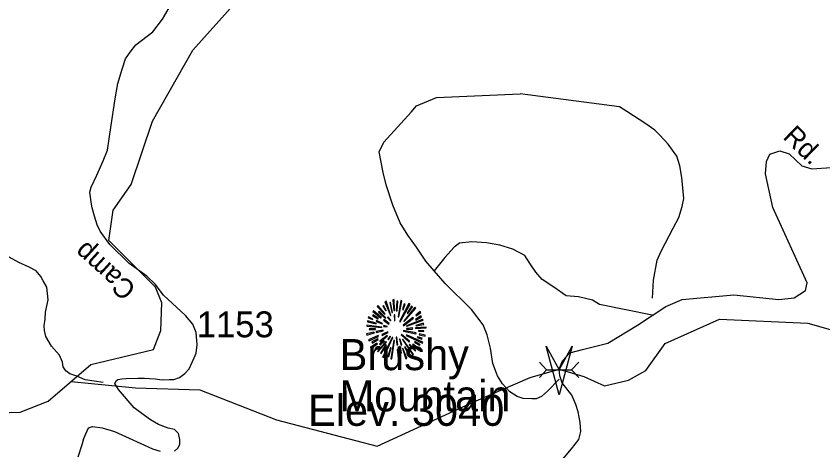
# Model space of a CAD drawing. Extents: x 990631 to 1056237, y 535999 to 585651.
# Drawn here: x 1010994 to 1014890, y 563508 to 565608 of the extents above; entities that cross this region are included whole.
import ezdxf

# ---------------------------------------------------------------- set-up
doc = ezdxf.new("R2010")
doc.units = 0
for name, color, linetype in [('Exist Geographical Mountain Summit CELL', 7, 'Continuous'), ('Exist Geographical Mountain Summit Elevation Number Label', 7, 'Continuous'), ('Exist Geographical Mountain Summit Label', 7, 'Continuous'), ('Exist Hydrographic Creek Single Shore', 7, 'Continuous'), ('Exist Road Non-System Type 51', 7, 'Continuous'), ('Exist Road Secondary Structure Pipe CELL', 7, 'Continuous'), ('Exist Road Secondary Structure Standard Bridge Attributed CELL', 7, 'Continuous'), ('Exist Road Secondary Type 41 Attributed', 7, 'Continuous'), ('Exist Road Secondary Type 51 Attributed', 7, 'Continuous'), ('Exist Road Secondary Type 51 Label', 7, 'Continuous'), ('Exist Road Secondary Type 51 Number Label', 7, 'Continuous')]:
    doc.layers.add(name, color=color, linetype=linetype)

msp = doc.modelspace()

# ---------------------------------------------------------------- linework, layer by layer
at = {"layer": 'Exist Geographical Mountain Summit CELL'}
for points in [[(1012736.6, 564205.5), (1012772.5, 564168.1), (1012775.8, 564170.6), (1012740.6, 564210.3)], [(1012764.1, 564207), (1012779.8, 564185.2), (1012781.6, 564186.6), (1012768.2, 564211)], [(1012775, 564228.8), (1012801.2, 564161.9), (1012804.2, 564163), (1012780.2, 564231.3)], [(1012808.9, 564176.8), (1012811.4, 564177.5), (1012802.4, 564225.5), (1012798, 564224.4)], [(1012813.6, 564238.2), (1012817.7, 564186.2), (1012820.9, 564186.6), (1012819.5, 564239.3)], [(1012829.6, 564184.1), (1012833.6, 564184.1), (1012837.2, 564231.3), (1012831.7, 564231.3)], [(1012841.6, 564155.7), (1012856.5, 564232.8), (1012851, 564234.6), (1012838.3, 564156.5)], [(1012844.8, 564133.9), (1012847.8, 564132.1), (1012896.4, 564216.7), (1012891, 564220.4)], [(1012859.3, 564191), (1012862.7, 564189.8), (1012872.1, 564216.7), (1012867.4, 564218.5)], [(1012903.4, 564207), (1012882.3, 564173.5), (1012885.2, 564172.4), (1012907.7, 564203.7)], [(1012715.1, 564161.9), (1012740.9, 564145.5), (1012743.1, 564148.1), (1012718, 564165.9)], [(1012716.2, 564180.8), (1012755.8, 564150.3), (1012758, 564152.5), (1012719.9, 564185.2)], [(1012744.5, 564177.9), (1012777.2, 564148.8), (1012779.4, 564151), (1012747.4, 564183)], [(1012865.9, 564135.4), (1012868.1, 564133.2), (1012923.7, 564197.5), (1012919.7, 564202.2)], [(1012923.7, 564163.4), (1012925.5, 564160.8), (1012948.4, 564177.1), (1012944.8, 564180.8)], [(1012690.4, 564131.7), (1012731.8, 564122.3), (1012732.9, 564125.6), (1012691.5, 564136.4)], [(1012693.3, 564151), (1012715.8, 564142.3), (1012716.9, 564145.2), (1012694.8, 564156.1)], [(1012731.8, 564133.9), (1012762.3, 564121.9), (1012763.5, 564124.1), (1012734, 564138)], [(1012768.2, 564139.4), (1012793.3, 564120.4), (1012795.4, 564123.3), (1012770.7, 564142.6)], [(1012787.8, 564152.5), (1012801.6, 564136), (1012803.8, 564138.2), (1012791.1, 564155.4)], [(1012819.1, 564164.8), (1012820.5, 564135.7), (1012823.1, 564136), (1012823.1, 564165.2)], [(1012862.7, 564115.4), (1012864.5, 564112.9), (1012913.1, 564148.8), (1012909.9, 564153.2)], [(1012879.7, 564112.5), (1012880.8, 564110.3), (1012958.9, 564139), (1012957.1, 564143.7)], [(1012923.7, 564140.5), (1012951.3, 564155.4), (1012948.4, 564160.4), (1012922.3, 564143)], [(1012687.8, 564110.7), (1012759.8, 564103.7), (1012760.1, 564106.6), (1012687.8, 564115.7)], [(1012699.9, 564093.2), (1012729.6, 564094.7), (1012729.6, 564098.3), (1012698.8, 564098.3)], [(1012732.2, 564084.2), (1012733.3, 564079.4), (1012766.4, 564087.8), (1012765.7, 564091.4)], [(1012768.5, 564109.6), (1012785.6, 564107.4), (1012786, 564109.6), (1012769.3, 564113.9)], [(1012864.1, 564086), (1012924.8, 564074), (1012925.9, 564078.3), (1012865.2, 564089.6)], [(1012878.7, 564099.8), (1012878.7, 564096.9), (1012908.8, 564096.9), (1012909.5, 564101.9)], [(1012921.9, 564098.7), (1012974.2, 564101.9), (1012974.6, 564106.6), (1012922.3, 564101.9)], [(1012925.5, 564112.5), (1012962.3, 564119), (1012960.8, 564124.5), (1012924.1, 564114.7)], [(1012936.8, 564086.7), (1012963.3, 564084.5), (1012963.3, 564088.8), (1012937.2, 564089.9)], [(1012686.4, 564072.9), (1012687.8, 564067.8), (1012723.9, 564078.3), (1012721.7, 564081.6)], [(1012696.2, 564045.2), (1012698.8, 564040.6), (1012744.2, 564060.5), (1012742.7, 564065.2)], [(1012713.7, 564029.3), (1012742.7, 564046), (1012740.6, 564049.6), (1012711.5, 564034.3)], [(1012750, 564038.7), (1012752.9, 564035), (1012787.4, 564063.4), (1012785.6, 564066)], [(1012759.8, 564070), (1012762, 564065.2), (1012790.7, 564080.5), (1012789.7, 564083.8)], [(1012781.6, 563998.8), (1012786, 563997), (1012812.5, 564055.4), (1012810, 564056.2)], [(1012788.5, 564048.1), (1012791.8, 564045.2), (1012802, 564061.6), (1012800.1, 564063)], [(1012828.5, 564057.3), (1012832.5, 564020.2), (1012836.9, 564020.5), (1012831.7, 564058)], [(1012844.5, 564048.5), (1012853.2, 564018.7), (1012857.2, 564020.5), (1012846.6, 564049.6)], [(1012852.9, 564068.9), (1012891.4, 564033.6), (1012893.9, 564038), (1012854.7, 564071.1)], [(1012877.9, 564066.4), (1012956.1, 564028.2), (1012957.9, 564033.6), (1012879.4, 564069.2)], [(1012931.4, 564056.2), (1012952.4, 564048.1), (1012954.2, 564052.5), (1012932.8, 564059.4)], [(1012940.8, 564069.6), (1012969.1, 564062.3), (1012969.8, 564067.8), (1012941.8, 564074)], [(1012707.5, 564008.5), (1012710.4, 564004.5), (1012738.8, 564025.6), (1012736.2, 564028.9)], [(1012738.4, 563988.9), (1012741.3, 563986.4), (1012782, 564034), (1012779.1, 564036.1)], [(1012753.7, 564020.2), (1012772.9, 564038.3), (1012769.6, 564040.6), (1012749.2, 564023.4)], [(1012778.4, 564020.2), (1012753.3, 563980.9), (1012756.5, 563978.4), (1012782.4, 564018)], [(1012803, 563953.3), (1012807.8, 563952.2), (1012820.5, 564041.6), (1012817.3, 564042.4)], [(1012854.3, 563982), (1012848.8, 564011.9), (1012845.6, 564011.9), (1012850, 563980.9)], [(1012859, 564046.3), (1012909.5, 563971.5), (1012913.1, 563974.4), (1012861.5, 564047.4)], [(1012869.5, 564009.2), (1012885.5, 563979.8), (1012889.6, 563982), (1012873.2, 564010.7)], [(1012891.4, 564020.5), (1012921.5, 563991.4), (1012924.8, 563994), (1012893.6, 564023)], [(1012908.1, 564021.2), (1012938.6, 563995.4), (1012941.8, 563999.1), (1012909.9, 564023.8)], [(1012917.2, 564032.2), (1012942.2, 564019.1), (1012944.8, 564022.7), (1012919.4, 564036.1)], [(1012763.5, 563961.7), (1012768.2, 563958.8), (1012779.1, 563983.5), (1012775.8, 563985.7)], [(1012793.3, 563963.5), (1012805.2, 564006.3), (1012801.6, 564006.7), (1012788.9, 563964.5)], [(1012834.7, 563998.8), (1012838.3, 563956.3), (1012842.3, 563957.3), (1012839, 563998.8)], [(1012859, 564003.5), (1012876.5, 563953.7), (1012880.8, 563955.5), (1012861.9, 564004.2)]]:
    msp.add_lwpolyline(points, close=True, dxfattribs=at)
at = {"layer": 'Exist Hydrographic Creek Single Shore'}
for points in [[(1009844.2, 563909.7), (1010249.7, 563813), (1010397.3, 563741.1), (1010754.1, 563687.9), (1011012.9, 563695.8), (1011148.1, 563748.9), (1011354.1, 563925.3), (1011656.7, 563997.9), (1011693.2, 564089.1), (1011697.7, 564223.5), (1011666.9, 564299.6), (1011440.8, 564524.1), (1011462.4, 564671.4), (1011549.9, 564794.3), (1011651.8, 565100.7), (1011846.8, 565444.7), (1012363.6, 566021.8)], [(1009844.2, 563909.7), (1010249.7, 563813), (1010397.3, 563741.1), (1010754.1, 563687.9), (1011012.9, 563695.8), (1011148.1, 563748.9), (1011354.1, 563925.3), (1011656.7, 563997.9), (1011693.2, 564089.1), (1011697.7, 564223.5), (1011666.9, 564299.6), (1011440.8, 564524.1), (1011462.4, 564671.4), (1011549.9, 564794.3), (1011651.8, 565100.7), (1011846.8, 565444.7), (1012363.6, 566021.8)], [(1011259.3, 563842.7), (1011570.5, 563813.5), (1011881.6, 563803.7), (1012251.2, 563657.8), (1012737.4, 563531.3), (1013204.1, 563745.4), (1013476.4, 563862.1), (1013616, 563902.9), (1013736.1, 563868.2), (1013836.2, 563823.2), (1013951.5, 563850.3), (1014035.6, 563895.9), (1014127.9, 564027.5), (1014390.5, 564144.3), (1014818.3, 564124.8), (1015129.5, 564037.3), (1015372.6, 564183.2), (1015644.9, 564134.6), (1015849.1, 563881.6), (1016335.3, 563871.9), (1016602.8, 563783.3)]]:
    msp.add_lwpolyline(points, dxfattribs=at)
at = {"layer": 'Exist Road Non-System Type 51'}
for points in [[(1013013.3, 564378), (1012972.8, 564425.4), (1012927.2, 564493), (1012884.9, 564550.4), (1012848.9, 564609.6), (1012813.8, 564694.9), (1012781, 564794), (1012767, 564852.5), (1012746.4, 564953.4), (1012769.8, 564999.4), (1012900.9, 565144.3), (1012928, 565174.3), (1013023.7, 565216), (1013427.4, 565232.6)], [(1014102, 565034.1), (1014078.7, 565056.9), (1014035.7, 565088.4), (1013943.7, 565147.5), (1013908.3, 565170.6), (1013427.4, 565232.6)], [(1014067.8, 564246.7), (1014072.5, 564332.6), (1014089.9, 564430.1), (1014109.3, 564473.5), (1014167, 564583.6), (1014194.6, 564634.9), (1014210.5, 564688.4), (1014217.9, 564728), (1014209.1, 564828.4), (1014199.1, 564884.9), (1014184.6, 564931.4), (1014142.6, 564990.6), (1014102, 565034.1)], [(1014065.1, 564163.4), (1013811.2, 564215.3), (1013777.2, 564236.7), (1013709.3, 564252.8), (1013649.6, 564256.7), (1013591.1, 564298.7), (1013534.2, 564336.7), (1013503.5, 564371.7), (1013476.7, 564412.5), (1013450.1, 564451.4), (1013393.1, 564483.4), (1013329.7, 564501.4), (1013266.1, 564513.7), (1013194.2, 564518), (1013135.8, 564512), (1013109.2, 564492.9), (1013063.6, 564442.4), (1013013.3, 564378)], [(1011414.4, 563839), (1011326.8, 563852), (1011287.3, 563869.2), (1011253.6, 563880.3), (1011234, 563895.1), (1011220.6, 563913.6), (1011217.5, 563937.6), (1011202.5, 563970.1), (1011164, 564013.5), (1011137.5, 564060.3), (1011130.5, 564090.6), (1011129.2, 564112.7), (1011134.4, 564144.6), (1011135.5, 564178.6), (1011147.5, 564238.2), (1011141.5, 564298.5), (1011124.5, 564329), (1011113.2, 564351.3), (1011090.1, 564378.2), (1011056.7, 564395.2), (1011007.3, 564419), (1010960.2, 564444.6)], [(1013616.4, 563854.9), (1013560.4, 563797.4), (1013531.4, 563770.3), (1013505, 563759.1), (1013485, 563759.9), (1013443, 563761.3), (1013413.4, 563770.3), (1013378, 563793.4), (1013343.4, 563832.5), (1013318.6, 563871.5), (1013296.6, 563930.1), (1013285.1, 564004.6), (1013269.2, 564069.3), (1013248.7, 564117.9), (1013193.2, 564191.9), (1013065.3, 564316.1), (1013013.3, 564378)]]:
    msp.add_lwpolyline(points, dxfattribs=at)
at = {"layer": 'Exist Road Secondary Structure Pipe CELL'}
for p, q in [((1013520.9, 563937.3), (1013555.8, 563900.4)), ((1013711.7, 563937.3), (1013676.8, 563900.4)), ((1013520.9, 563863.5), (1013555.8, 563900.4)), ((1013555.8, 563900.4), (1013676.8, 563900.4)), ((1013711.7, 563863.5), (1013676.8, 563900.4))]:
    msp.add_line(p, q, dxfattribs=at)
at = {"layer": 'Exist Road Secondary Structure Standard Bridge Attributed CELL'}
msp.add_lwpolyline([(1013679.4, 564014), (1013616.3, 563778.5), (1013553.2, 564014), (1013616.3, 563900.4)], close=True, dxfattribs=at)
at = {"layer": 'Exist Road Secondary Type 41 Attributed'}
for points in [[(1011758.7, 563506.4), (1011774.4, 563522.1), (1011784.3, 563538.9), (1011784.3, 563563.7), (1011778.3, 563592.4), (1011758.5, 563612.2), (1011727.2, 563618.5), (1011681.3, 563635), (1011642.3, 563658.2), (1011613.2, 563679.2), (1011564.3, 563716), (1011487.3, 563804.6), (1011470.3, 563833.1), (1011477.9, 563848.7), (1011485.1, 563853.1), (1011503.9, 563856), (1011524.2, 563857.4), (1011582.1, 563860.3), (1011613.9, 563858.9), (1011637, 563857.6), (1011665, 563856.6), (1011698.9, 563851.5), (1011732.9, 563852.4), (1011755.8, 563853.1), (1011781.9, 563863.2), (1011807.9, 563882), (1011829.6, 563905.2), (1011854.2, 563957.4), (1011863.5, 563980.7), (1011868.4, 564020.3), (1011863.5, 564080.7), (1011847.6, 564120.4), (1011812, 564162.5), (1011705, 564260.5), (1011665.4, 564314), (1011624.8, 564351.7), (1011539.6, 564413.1), (1011446.5, 564505.2), (1011399, 564569.1), (1011384.2, 564600.8), (1011371.3, 564642.4), (1011360.1, 564682), (1011357.2, 564699.4), (1011349.5, 564757.3), (1011356.4, 564782.1), (1011383.2, 564840.5), (1011414.2, 564909), (1011434.7, 564960.9), (1011450.5, 565070.8), (1011472.3, 565209), (1011485.1, 565282.8), (1011506.4, 565352.9), (1011522.3, 565402.1), (1011543.6, 565434.9), (1011572.3, 565469.5), (1011653.5, 565531.9), (1011701.1, 565593.3), (1011784.3, 565738)], [(1011293, 563480), (1011314.8, 563544.3), (1011320.8, 563568.1), (1011329.7, 563590.9), (1011343.6, 563619.6), (1011362.4, 563626.6), (1011408.9, 563619.6), (1011468.3, 563601.8), (1011539.6, 563569.1), (1011652.5, 563518.6), (1011689.2, 563507.2)]]:
    msp.add_lwpolyline(points, dxfattribs=at)
at = {"layer": 'Exist Road Secondary Type 51 Attributed'}
for points in [[(1013730, 563998.4), (1013851.6, 564029.1), (1013994.4, 564115.7), (1014131.7, 564206.3), (1014210, 564239.3), (1014459.6, 564262.3), (1014677, 564239.7), (1014752.4, 564247.2), (1014806.8, 564283.5), (1014814.3, 564319.7), (1014648.3, 564683.7), (1014613.6, 564846.8), (1014618.1, 564905.7), (1014634.7, 564941.9), (1014683, 564957), (1014726.8, 564943.4), (1014788.7, 564886), (1014837, 564870.9), (1015003, 564881.5)], [(1013496.7, 563304.9), (1013676.3, 563517.8), (1013711.1, 563563.1), (1013721.6, 563602.4), (1013718.6, 563646.2), (1013709, 563696.3), (1013697.5, 563732.3), (1013677.8, 563777.6), (1013631.1, 563836.5), (1013620.5, 563871.2), (1013616, 563902.9), (1013632.6, 563943.7), (1013668.8, 563981.4), (1013730, 563998.4)]]:
    msp.add_lwpolyline(points, dxfattribs=at)

# ---------------------------------------------------------------- texts
at = {"layer": 'Exist Geographical Mountain Summit Elevation Number Label'}
msp.add_text('Elev. 3040', height=150, dxfattribs=at).set_placement((1012403.6, 563629.2))
msp.add_text('Elev. 3040', height=150, dxfattribs=at).set_placement((1012403.6, 563629.2))
at = {"layer": 'Exist Geographical Mountain Summit Label'}
for s, p in [('Brushy', (1012556.2, 563898.4)), ('Brushy', (1012556.2, 563898.4)), ('Mountain', (1012556.2, 563699.2)), ('Mountain', (1012556.2, 563699.2))]:
    msp.add_text(s, height=150, dxfattribs=at).set_placement(p)
at = {"layer": 'Exist Road Secondary Type 51 Label'}
for s, rotation, p in [('Rd.', 315.8845, (1014692.7, 565020.8)), ('Rd.', 315.8845, (1014692.7, 565020.8)), ('Camp', 137.7197, (1011579, 564297.6)), ('Camp', 137.7197, (1011579, 564297.6))]:
    msp.add_text(s, height=95, rotation=rotation, dxfattribs=at).set_placement(p)
at = {"layer": 'Exist Road Secondary Type 51 Number Label'}
msp.add_text('1153', height=125, dxfattribs=at).set_placement((1011866.1, 564057))

doc.saveas('drawing.dxf')
